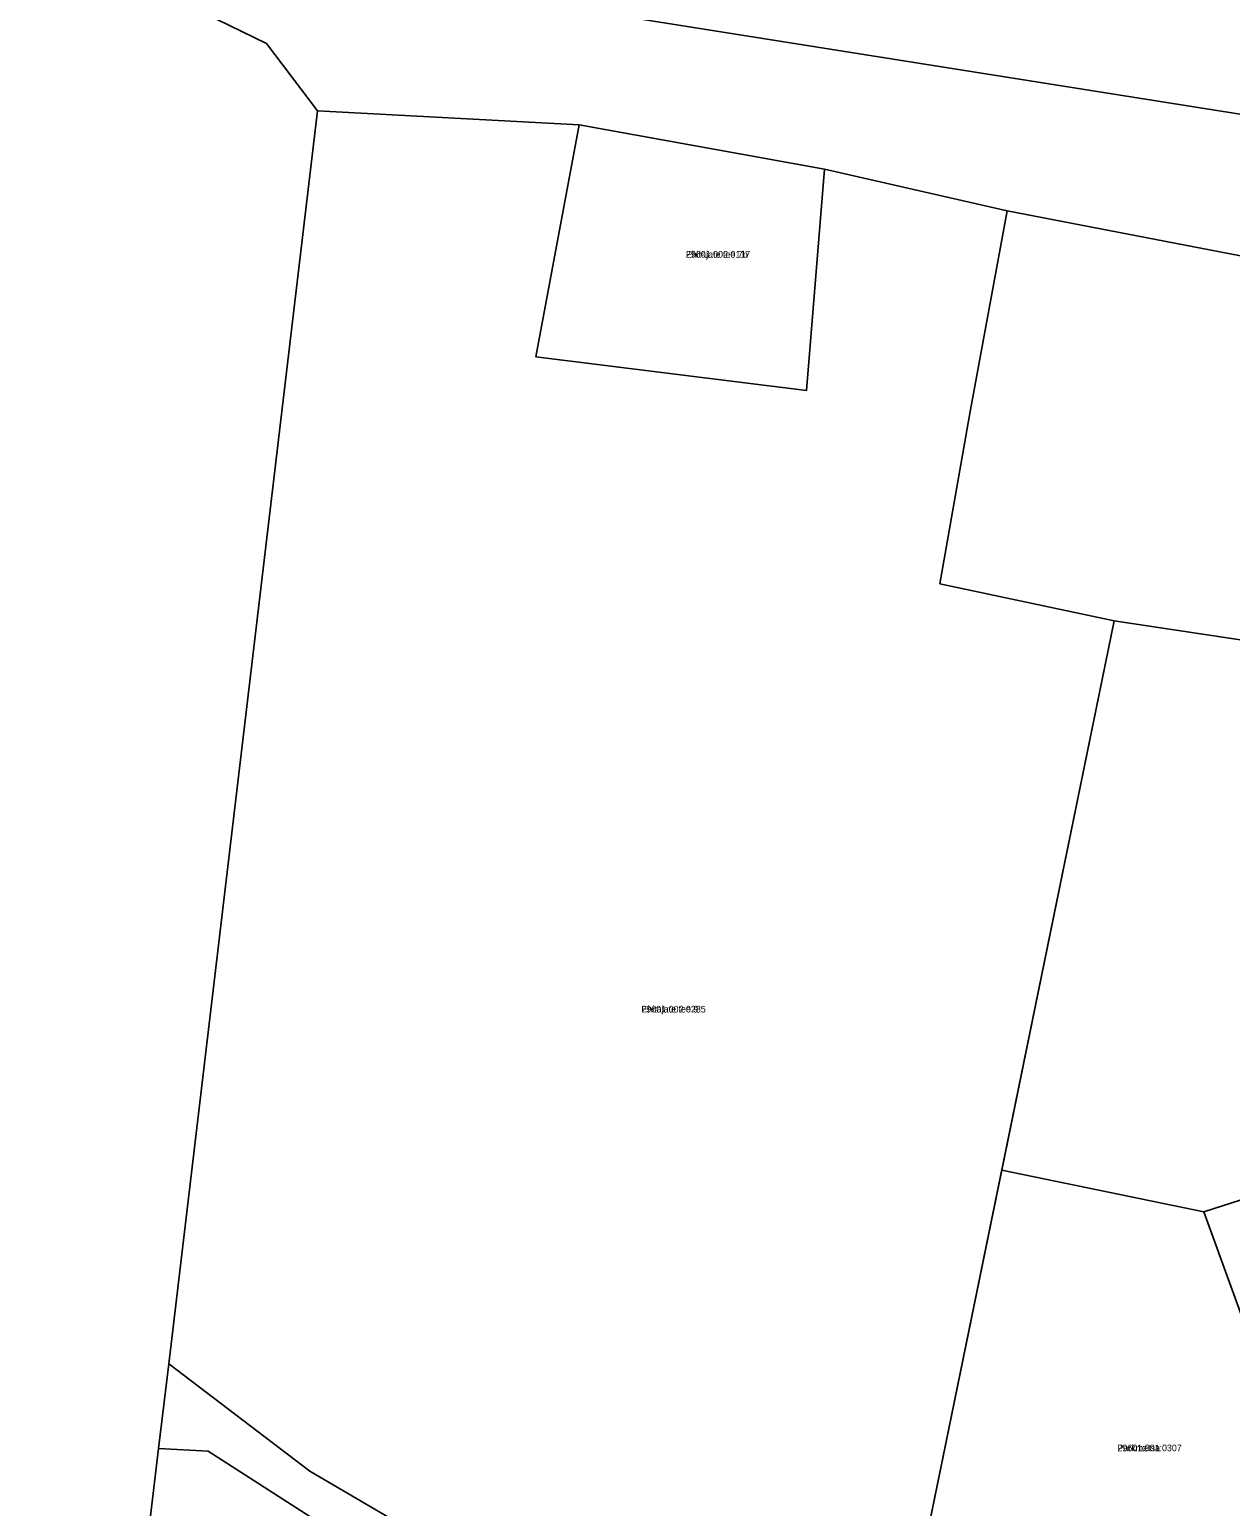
# Model space of a CAD drawing. Extents: x 518839 to 525192, y 6573164 to 6576561.
# Drawn here: x 522529.2 to 522800, y 6574963.2 to 6575296.1 of the extents above; entities that cross this region are included whole.
import ezdxf

# ---------------------------------------------------------------- set-up
doc = ezdxf.new("R2010")
doc.units = 0
for name, color, linetype in [('L_AADRESS', 7, 'Continuous'), ('PIIR', 7, 'Continuous'), ('TUNNUS', 7, 'Continuous')]:
    doc.layers.add(name, color=color, linetype=linetype)

msp = doc.modelspace()

# ---------------------------------------------------------------- linework, layer by layer
at = {"layer": 'PIIR'}
for points in [[(522853.45, 6575268.92), (522631.08, 6575304.25), (522583.02, 6575312.04), (522576.19, 6575315.11), (522565.94, 6575322.54), (522557.95, 6575332.39), (522552.73, 6575339.83), (522590.7, 6575417.16), (522666.44, 6575381.03), (522673.33, 6575377.74), (522681.33, 6575393.87), (522698.51, 6575428.49), (522631.66, 6575459.79), (522691.1, 6575580.92), (522720.98, 6575566.8), (522816.82, 6575521.48)], [(522900.52, 6575226.16), (522749.68, 6575255.25), (522708.49, 6575264.65), (522653.18, 6575274.63), (522594.13, 6575277.81), (522582.64, 6575292.96), (522552.04, 6575307.91), (522529.22, 6575338.57), (522540.82, 6575348.29), (522544.58, 6575351.44), (522552.73, 6575339.83), (522557.95, 6575332.39), (522565.94, 6575322.54), (522576.19, 6575315.11), (522583.02, 6575312.04), (522631.08, 6575304.25), (522853.45, 6575268.92)], [(522552.04, 6575307.91), (522582.64, 6575292.96), (522594.13, 6575277.81), (522560.6, 6574995.36), (522558.33, 6574976.27), (522554.49, 6574943.99)]]:
    msp.add_lwpolyline(points, dxfattribs=at)
for points in [[(522594.13, 6575277.81), (522653.18, 6575274.63), (522643.43, 6575222.37), (522704.46, 6575214.76), (522708.49, 6575264.65), (522749.68, 6575255.25), (522741.36, 6575209.99), (522734.5, 6575171.21), (522773.81, 6575162.85), (522725.33, 6574926.11), (522705.01, 6574921.1), (522686, 6574922.8), (522656.89, 6574933.47), (522592.43, 6574971.18), (522560.6, 6574995.36)], [(522653.18, 6575274.63), (522708.49, 6575264.65), (522704.46, 6575214.76), (522643.43, 6575222.37)], [(522749.68, 6575255.25), (522900.52, 6575226.16), (522888.15, 6575145.61), (522773.81, 6575162.85), (522734.5, 6575171.21), (522741.36, 6575209.99)], [(522773.81, 6575162.85), (522888.15, 6575145.61), (522882.51, 6575109.88), (522849.19, 6575114.97), (522846.68, 6575118.39), (522847.81, 6575125.79), (522828.53, 6575128.73), (522825.41, 6575108.53), (522880.95, 6575100), (522873.89, 6575055.31), (522851.62, 6575048.12), (522794.04, 6575029.6), (522748.45, 6575038.99)], [(522794.04, 6575029.6), (522851.62, 6575048.12), (522871.85, 6574992.21), (522814.7, 6574972.75)], [(522748.45, 6575038.99), (522794.04, 6575029.6), (522814.7, 6574972.75), (522871.85, 6574992.21), (522897.07, 6574955.8), (522885.59, 6574952.93), (522845, 6574942.81), (522778.15, 6574926.2), (522770.44, 6574924.25), (522722.5, 6574912.3), (522723.6, 6574917.68), (522725.33, 6574926.11)], [(522560.6, 6574995.36), (522592.43, 6574971.18), (522656.89, 6574933.47), (522686, 6574922.8), (522705.01, 6574921.1), (522725.33, 6574926.11), (522723.6, 6574917.68), (522697.29, 6574913.83), (522683.37, 6574910.97), (522682.62, 6574914.53), (522657.66, 6574921.95), (522634.19, 6574934.9), (522608.9, 6574950.59), (522606.14, 6574952.12), (522569.54, 6574975.64), (522558.33, 6574976.27)], [(522558.33, 6574976.27), (522569.54, 6574975.64), (522606.14, 6574952.12), (522589.83, 6574935.6), (522566.01, 6574920.76), (522554.47, 6574943.99)]]:
    msp.add_lwpolyline(points, close=True, dxfattribs=at)

# ---------------------------------------------------------------- texts
at = {"layer": 'L_AADRESS'}
for s, p in [('Ehitajate tee 7b', (522677.24, 6575244.7)), ('Ehitajate tee 9', (522667.21, 6575074.55)), ('Parkmetsa', (522774.56, 6574975.65))]:
    msp.add_text(s, height=1.5, dxfattribs=at).set_placement(p)
at = {"layer": 'TUNNUS'}
for s, p in [('29601:002:0117', (522677.24, 6575244.7)), ('29601:002:0285', (522667.21, 6575074.55)), ('29601:001:0307', (522774.56, 6574975.65))]:
    msp.add_text(s, height=1.5, dxfattribs=at).set_placement(p)

doc.saveas('drawing.dxf')
